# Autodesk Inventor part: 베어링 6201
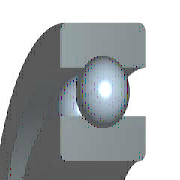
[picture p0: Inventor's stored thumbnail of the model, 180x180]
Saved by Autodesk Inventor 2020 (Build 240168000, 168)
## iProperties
Company: 한국ATC센터
Created: 2015-12
Part Number: 베어링 6201
Material: 강철, 연강
Description: 깊은 그루브 볼 베어링
Document SubType Name: Modeling
Standard: KS B 2023
Designer: mdu
Standards Organization: KS
Language: ko-KR
Size Designation: 6201 - 12 x 32 x 10
Categories: <MemberInstance><Categories><Category DisplayName="샤프트 부품" InternalName="7f7aeb1f-a693-4053-b835-cee3144e0d98" Mnemonic="SHFT"><Category DisplayName="베어링" Inter
Density: 7.86 g/cm^3
Mass: 36.8026 g
Surface Area: 42.5728 cm^2
Volume: 4.68226 cm^3
Appearance: 노란색
IsCustomPart: 1
Author: mdu
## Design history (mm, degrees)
sketch "스케치" dims "d0" = 5.2 (= -0.26 x WD + 0.26 x BD)
  geometry: L1 (2.4, 11)-(7.6, 11); L2 (5, 11)-(5, 8.4); L3 (5, 11)-(5, 13.6); L4 (3.068, 9.26)-(0, 9.26); L5 (0, 6)-(10, 6); L6 (3.068, 12.74)-(0, 12.74); L7 (0, 16)-(10, 16); L8 (10, 6)-(10, 9.26); L9 (6.932, 9.26)-(10, 9.26); L10 (6.932, 12.74)-(10, 12.74); L11 (10, 16)-(10, 12.74); L12 (-1.4, 0)-(8.4, 0) reference; L13 (0, -0.3)-(0, 5.3) reference
  constraints: 22 end point, 4 point on line, 2 collinear, 2 perpendicular, 2 symmetric about line, 1 midpoint, 1 parallel, 14 other
  dimensions: "d9" = 12 diameter of L5 L12 (= WD); "d11" = 32 diameter of L7 L12 (= BD); "d12" = 10 distance between parallel lines of L8 L13 (= KB); "d13" = 18.52 diameter of L9 L12 (= 0.326 x BD + 0.674 x WD)
revolve "본체" stored, may be unused: angle "d6" = 90 deg
revolve "볼" stored, may be unused: angle "d7" = 90 deg
pattern_circular "IDS_ARRAYBALL[SIMPL:T]" dims angle "d3" = 360 deg
body "Solid1"
fillet "모깎기1" dims "d1" = 0.6 (= KRS)
other parameters: "WD" = 12 [user parameter; used in 5 equation terms], "BD" = 32 [user parameter; used in 5 equation terms], "KB" = 10 [user parameter; used in 1 equation term], "KRS" = 0.6 [user parameter; used in 1 equation term], "d4" = 0, "d5" = 0, "d8" = 0, "d14" = 0, "d15" = 0, "BBA" = 0 [user parameter], "BC0" = 3100000 [user parameter], "BC" = 6890000 [user parameter], "BR" = 16 (= 0.5 x BD) [user parameter], "WR" = 6 (= 0.5 x WD) [user parameter]
